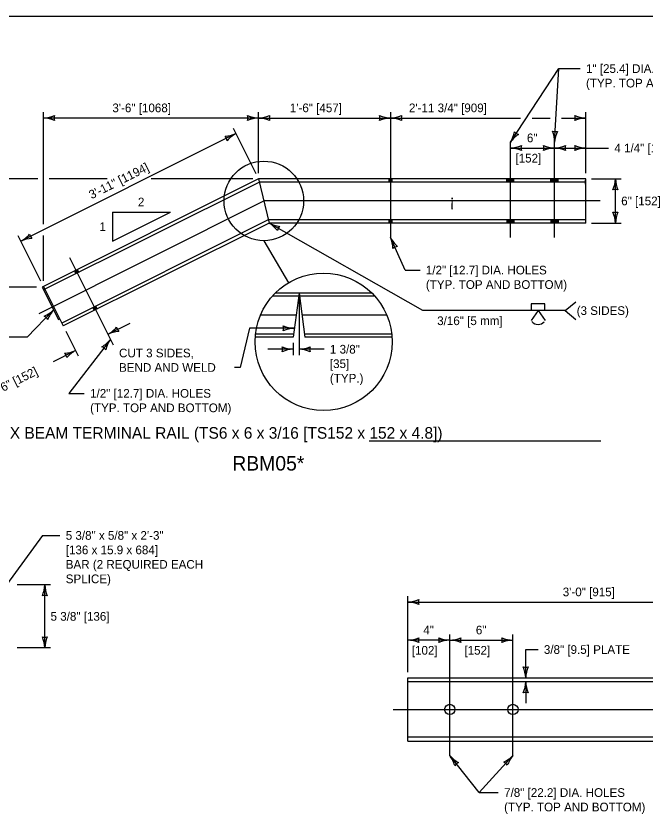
# Model space of a CAD drawing. Extents: x 49991.4 to 50021, y 49987.6 to 50011.4.
# Drawn here: x 50009.79 to 50014.14, y 49993.45 to 49999 of the extents above; entities that cross this region are included whole.
import ezdxf

# ---------------------------------------------------------------- set-up
doc = ezdxf.new("R2010")
doc.units = 0
for name, color, linetype in [('Level 1', 7, 'Continuous'), ('Level 2', 7, 'Continuous'), ('Level 3', 7, 'Continuous'), ('Level 4', 7, 'Continuous'), ('Level 5', 7, 'Continuous')]:
    doc.layers.add(name, color=color, linetype=linetype)

msp = doc.modelspace()

# ---------------------------------------------------------------- linework, layer by layer
at = {"layer": 'Level 1'}
for p, q in [((50011.4634, 49997.8746), (50009.9679, 49997.1269)), ((50011.4634, 49997.8746), (50011.5353, 49997.5698)), ((50013.2106, 49997.8746), (50011.4634, 49997.8746)), ((50013.7246, 49997.8746), (50013.2108, 49997.8746)), ((50013.7246, 49997.5698), (50013.7246, 49997.8746)), ((50011.5353, 49997.5698), (50010.1132, 49996.8588)), ((50013.2106, 49997.5698), (50011.5353, 49997.5698)), ((50013.7246, 49997.5698), (50013.2109, 49997.5698)), ((50009.9769, 49997.1314), (50009.9679, 49997.1269)), ((50009.9679, 49997.1269), (50010.08, 49996.9027)), ((50009.9769, 49997.1314), (50010.1132, 49996.8588)), ((50012.2451, 49997.0864), (50011.5793, 49997.0864)), ((50011.7426, 49997.0864), (50011.7014, 49996.7816)), ((50011.7426, 49997.0864), (50011.7839, 49996.7816)), ((50010.08, 49996.9027), (50010.089, 49996.9072)), ((50011.7014, 49996.7816), (50011.4395, 49996.7816)), ((50012.3849, 49996.7816), (50011.7839, 49996.7816)), ((50012.4943, 49994.4284), (50015.1145, 49994.4284)), ((50012.4943, 49993.9918), (50012.4943, 49994.4284)), ((50012.4943, 49993.9918), (50015.1145, 49993.9918))]:
    msp.add_line(p, q, dxfattribs=at)
msp.add_lwpolyline([(49999.3835, 49998.9992), (50016.7501, 49998.9992), (50016.7501, 49987.7988), (49999.3835, 49987.7988)], close=True, dxfattribs=at)
for centre in [(50012.7844, 49994.21), (50013.2211, 49994.21)]:
    msp.add_circle(centre, 0.0356, dxfattribs=at)
at = {"layer": 'Level 2'}
msp.add_line((50012.228, 49996.0643), (50013.8293, 49996.0643), dxfattribs=at)
at = {"layer": 'Level 3'}
for p, q in [((50013.2033, 49998.1278), (50013.538, 49998.6364)), ((50013.5079, 49998.1278), (50013.538, 49998.6364)), ((50013.538, 49998.6364), (50013.6861, 49998.6364)), ((50009.9769, 49997.5627), (50009.9769, 49998.3351)), ((50011.4634, 49998.2951), (50009.9769, 49998.2951)), ((50011.4634, 49997.9146), (50011.4634, 49998.3351)), ((50011.4634, 49998.2951), (50012.3758, 49998.2951)), ((50012.3758, 49998.2951), (50013.2734, 49998.2951)), ((50013.3534, 49998.2951), (50013.4778, 49998.2951)), ((50013.5578, 49998.2951), (50013.7246, 49998.2951)), ((50013.7246, 49997.9146), (50013.7246, 49998.3351)), ((50011.3068, 49998.1877), (50009.8203, 49997.4444)), ((50011.4455, 49997.9104), (50011.289, 49998.2235)), ((50013.2033, 49998.0878), (50013.5079, 49998.0878)), ((50013.5079, 49998.0878), (50013.7246, 49998.0878)), ((50013.7246, 49998.0878), (50013.8821, 49998.0878)), ((50009.9369, 49997.8746), (50009.5533, 49997.8746)), ((50010.4161, 49997.8746), (50010.0169, 49997.8746)), ((50011.4234, 49997.8746), (50010.7207, 49997.8746)), ((50013.7646, 49997.8746), (50013.9694, 49997.8746)), ((50013.9294, 49997.5698), (50013.9294, 49997.8746)), ((50010.4537, 49997.6451), (50010.4537, 49997.4446)), ((50010.4537, 49997.6451), (50010.8548, 49997.6451)), ((50010.4537, 49997.4446), (50010.8548, 49997.6451)), ((50012.5977, 49996.9648), (50011.5353, 49997.5698)), ((50013.7646, 49997.5698), (50013.9694, 49997.5698)), ((50009.959, 49997.1672), (50009.8025, 49997.4802)), ((50009.9769, 49997.1714), (50009.9769, 49997.4827)), ((50012.4762, 49997.2448), (50012.3758, 49997.4698)), ((50012.3804, 49997.4595), (50012.3804, 49997.4595)), ((50011.4993, 49997.4476), (50011.6694, 49997.156)), ((50012.4762, 49997.2448), (50012.5792, 49997.2448)), ((50009.9279, 49997.1269), (50009.5533, 49997.1269)), ((50013.3481, 49997.012), (50013.3481, 49996.9648)), ((50013.4414, 49997.012), (50013.3481, 49997.012)), ((50013.4414, 49996.9648), (50013.4414, 49997.012)), ((50013.5816, 49996.9648), (50013.6548, 49997.0262)), ((50010.0467, 49996.9693), (50009.8642, 49996.7819)), ((50013.5816, 49996.9648), (50012.5977, 49996.9648)), ((50013.3948, 49996.9648), (50013.3463, 49996.8971)), ((50013.3948, 49996.9648), (50013.4433, 49996.8971)), ((50013.5816, 49996.9648), (50013.6548, 49996.9034)), ((50010.4216, 49996.801), (50010.5767, 49996.8786)), ((50011.4008, 49996.8428), (50011.336, 49996.572)), ((50011.7097, 49996.8428), (50011.4008, 49996.8428)), ((50010.1311, 49996.823), (50010.2159, 49996.6534)), ((50009.8642, 49996.7819), (50009.7393, 49996.7819)), ((50010.4395, 49996.7652), (50010.1522, 49996.3934)), ((50011.7014, 49996.7416), (50011.7014, 49996.658)), ((50010.198, 49996.6892), (50010.0429, 49996.6117)), ((50011.7014, 49996.698), (50011.528, 49996.698)), ((50011.916, 49996.698), (50011.7426, 49996.698)), ((50011.336, 49996.572), (50011.296, 49996.572)), ((50010.1522, 49996.3934), (50010.2587, 49996.3934)), ((50012.4941, 49994.4684), (50012.4941, 49994.9918)), ((50012.4943, 49994.9518), (50015.1173, 49994.9518)), ((50012.7844, 49994.6885), (50012.4941, 49994.6885)), ((50012.7844, 49994.6885), (50013.2211, 49994.6885)), ((50013.3095, 49994.4284), (50013.3095, 49994.6238)), ((50013.3095, 49994.6238), (50013.3949, 49994.6238)), ((50013.3095, 49994.4012), (50013.3095, 49994.2528)), ((50012.9874, 49993.6359), (50012.7844, 49993.8918)), ((50012.9874, 49993.6359), (50013.2211, 49993.8918)), ((50012.9874, 49993.636), (50013.12, 49993.636))]:
    msp.add_line(p, q, dxfattribs=at)
for points in [[(50009.969, 49995.4121), (50009.7202, 49995.0713)], [(50009.969, 49995.4121), (50010.0904, 49995.4121)], [(50010.0254, 49995.0713), (50009.7954, 49995.0713)], [(50009.9854, 49994.6345), (50009.9854, 49995.0713)], [(50010.0254, 49994.6345), (50009.7954, 49994.6345)]]:
    msp.add_lwpolyline(points, dxfattribs=at)
for centre, radius in [((50011.4993, 49997.7222), 0.2747), ((50011.9122, 49996.7492), 0.4738)]:
    msp.add_circle(centre, radius, dxfattribs=at)
for centre, radius, start, end in [((50009.9677, 49998.5172), 0.2223, 272.3605, 292.544), ((50009.9654, 49998.0624), 0.233, 67.9228, 87.1727), ((50010.1051, 49998.2951), 0.0548, 162.1388, 197.8612), ((50011.3352, 49998.2951), 0.0548, 342.1388, 17.8612), ((50011.4749, 49998.5278), 0.233, 247.9228, 267.1727), ((50011.4725, 49998.0729), 0.2223, 92.3605, 112.544), ((50011.4542, 49998.5172), 0.2223, 272.3605, 292.544), ((50011.4519, 49998.0624), 0.233, 67.9228, 87.1727), ((50011.5916, 49998.2951), 0.0548, 162.1388, 197.8612), ((50012.2475, 49998.2951), 0.0548, 342.1388, 17.8612), ((50012.3873, 49998.5278), 0.233, 247.9228, 267.1727), ((50012.3849, 49998.0729), 0.2223, 92.3605, 112.544), ((50012.3666, 49998.5172), 0.2223, 272.3605, 292.544), ((50012.3643, 49998.0624), 0.233, 67.9228, 87.1727), ((50012.504, 49998.2951), 0.0548, 162.1388, 197.8612), ((50013.5964, 49998.2951), 0.0548, 342.1388, 17.8612), ((50013.7361, 49998.5278), 0.233, 247.9228, 267.1727), ((50013.7337, 49998.0729), 0.2223, 92.3605, 112.544), ((50011.213, 49998.401), 0.233, 274.4879, 293.7377), ((50011.4144, 49997.9931), 0.2223, 118.9255, 139.109), ((50013.0026, 49998.2461), 0.233, 329.4806, 348.7305), ((50013.3839, 49997.9981), 0.2223, 124.1093, 144.2928), ((50013.2738, 49998.2349), 0.0548, 218.7921, 254.5145), ((50013.5155, 49998.2558), 0.0548, 248.751, 284.4734), ((50013.2749, 49998.1301), 0.233, 359.4395, 18.6894), ((50013.7291, 49998.1056), 0.2223, 154.0682, 174.2517), ((50011.1922, 49998.1303), 0.0548, 8.7039, 44.4262), ((50013.1942, 49998.31), 0.2223, 272.3605, 292.544), ((50013.1918, 49997.8551), 0.233, 67.9228, 87.1727), ((50013.3316, 49998.0878), 0.0548, 162.1388, 197.8612), ((50013.3797, 49998.0878), 0.0548, 342.1388, 17.8612), ((50013.5194, 49998.3205), 0.233, 247.9228, 267.1727), ((50013.517, 49997.8657), 0.2223, 92.3605, 112.544), ((50013.4987, 49998.31), 0.2223, 272.3605, 292.544), ((50013.4964, 49997.8551), 0.233, 67.9228, 87.1727), ((50013.6361, 49998.0878), 0.0548, 162.1388, 197.8612), ((50013.5964, 49998.0878), 0.0548, 342.1388, 17.8612), ((50013.7361, 49998.3205), 0.233, 247.9228, 267.1727), ((50013.7337, 49997.8657), 0.2223, 92.3605, 112.544), ((50013.6967, 49997.8861), 0.233, 337.9228, 357.1727), ((50014.1516, 49997.8838), 0.2223, 182.3605, 202.544), ((50013.9294, 49997.7464), 0.0548, 72.1388, 107.8612), ((50013.7073, 49997.5607), 0.2223, 2.3605, 22.544), ((50013.9294, 49997.698), 0.0548, 252.1388, 287.8612), ((50014.1622, 49997.5583), 0.233, 157.9228, 177.1727), ((50011.6373, 49997.7674), 0.2223, 242.6979, 262.8814), ((50011.4102, 49997.3733), 0.233, 38.2602, 57.5101), ((50011.6467, 49997.5064), 0.0548, 132.4762, 168.1986), ((50009.7128, 49997.639), 0.2223, 298.9255, 319.109), ((50009.9141, 49997.2312), 0.233, 94.4879, 113.7377), ((50009.935, 49997.5018), 0.0548, 188.7039, 224.4262), ((50012.1692, 49997.3876), 0.2223, 1.5178, 21.7013), ((50012.5836, 49997.5752), 0.233, 206.8891, 226.139), ((50012.428, 49997.3528), 0.0548, 96.2006, 131.923), ((50009.888, 49997.1399), 0.233, 293.6888, 312.9386), ((50010.2123, 49996.8209), 0.2223, 138.1264, 158.3099), ((50009.9573, 49996.8774), 0.0548, 27.9048, 63.6271), ((50010.3072, 49997.004), 0.233, 299.3924, 318.6422), ((50010.5363, 49996.8584), 0.0548, 188.7039, 224.4262), ((50011.5815, 49996.8428), 0.0548, 342.1388, 17.8612), ((50011.7212, 49997.0755), 0.233, 247.9228, 267.1727), ((50011.7188, 49996.6206), 0.2223, 92.3605, 112.544), ((50013.395, 49996.9255), 0.0566, 220.7558, 318.7312), ((50010.5127, 49996.5982), 0.2223, 94.0211, 114.2046), ((50010.2693, 49996.9083), 0.2223, 299.7681, 319.9516), ((50010.6307, 49996.6321), 0.233, 145.1394, 164.3893), ((50010.1068, 49996.892), 0.2223, 274.0211, 294.2046), ((50010.3123, 49996.4862), 0.233, 119.3924, 138.6422), ((50010.3611, 49996.6638), 0.0548, 34.4509, 70.1733), ((50011.5732, 49996.698), 0.0548, 342.1388, 17.8612), ((50011.7129, 49996.9307), 0.233, 247.9228, 267.1727), ((50011.7106, 49996.4759), 0.2223, 92.3605, 112.544), ((50011.7335, 49996.9202), 0.2223, 272.3605, 292.544), ((50011.7311, 49996.4653), 0.233, 67.9228, 87.1727), ((50011.8709, 49996.698), 0.0548, 162.1388, 197.8612), ((50010.0833, 49996.6319), 0.0548, 8.7039, 44.4262), ((50009.7633, 49995.0805), 0.2223, 337.456, 357.6395), ((50010.2181, 49995.0828), 0.233, 182.8273, 202.0772), ((50009.9854, 49994.9431), 0.0548, 72.1388, 107.8612), ((50012.4827, 49995.1845), 0.233, 272.8273, 292.0772), ((50012.6224, 49994.9518), 0.0548, 162.1388, 197.8612), ((50012.485, 49994.7297), 0.2223, 67.456, 87.6395), ((50009.9854, 49994.7627), 0.0548, 252.1388, 287.8612), ((50009.7527, 49994.623), 0.233, 2.8273, 22.0772), ((50010.2076, 49994.6253), 0.2223, 157.456, 177.6395), ((50012.4827, 49994.9212), 0.233, 272.8273, 292.0772), ((50012.485, 49994.4663), 0.2223, 67.456, 87.6395), ((50012.6224, 49994.6885), 0.0548, 162.1388, 197.8612), ((50012.7936, 49994.9106), 0.2223, 247.456, 267.6395), ((50012.6562, 49994.6885), 0.0548, 342.1388, 17.8612), ((50012.7959, 49994.4558), 0.233, 92.8273, 112.0772), ((50012.7729, 49994.9212), 0.233, 272.8273, 292.0772), ((50012.7753, 49994.4663), 0.2223, 67.456, 87.6395), ((50012.9126, 49994.6885), 0.0548, 162.1388, 197.8612), ((50013.2303, 49994.9106), 0.2223, 247.456, 267.6395), ((50013.0929, 49994.6885), 0.0548, 342.1388, 17.8612), ((50013.2326, 49994.4558), 0.233, 92.8273, 112.0772), ((50013.3095, 49994.5566), 0.0548, 252.1388, 287.8612), ((50013.0768, 49994.4169), 0.233, 2.8273, 22.0772), ((50013.5317, 49994.4192), 0.2223, 157.456, 177.6395), ((50013.0874, 49994.4104), 0.2223, 337.456, 357.6395), ((50013.5422, 49994.4127), 0.233, 182.8273, 202.0772), ((50013.3095, 49994.273), 0.0548, 72.1388, 107.8612), ((50012.6047, 49993.7609), 0.2223, 15.8845, 36.068), ((50012.9596, 49994.0454), 0.233, 221.2558, 240.5056), ((50013.0633, 49994.0483), 0.2223, 295.0486, 315.2321), ((50013.1347, 49993.7971), 0.0548, 29.7314, 65.4538), ((50013.4007, 49993.7433), 0.233, 140.4199, 159.6697), ((50012.8641, 49993.7913), 0.0548, 110.5673, 146.2897)]:
    msp.add_arc(centre, radius, start, end, dxfattribs=at)
at = {"layer": 'Level 4'}
for p, q in [((50011.4684, 49997.8531), (50009.9775, 49997.1077)), ((50013.7246, 49997.8531), (50011.4684, 49997.8531)), ((50012.3649, 49997.8531), (50012.3649, 49997.8746)), ((50012.3869, 49997.8689), (50012.3649, 49997.8689)), ((50012.3869, 49997.8639), (50012.3649, 49997.8639)), ((50012.3869, 49997.8589), (50012.3649, 49997.8589)), ((50012.3869, 49997.8531), (50012.3869, 49997.8746)), ((50013.1786, 49997.8531), (50013.1786, 49997.8747)), ((50013.2281, 49997.8689), (50013.1786, 49997.8689)), ((50013.2281, 49997.8639), (50013.1786, 49997.8639)), ((50013.2281, 49997.8589), (50013.1786, 49997.8589)), ((50013.2281, 49997.8531), (50013.2281, 49997.8747)), ((50013.4831, 49997.8531), (50013.4831, 49997.8746)), ((50013.5326, 49997.8689), (50013.4831, 49997.8689)), ((50013.5326, 49997.8639), (50013.4831, 49997.8639)), ((50013.5326, 49997.8589), (50013.4831, 49997.8589)), ((50013.5326, 49997.8531), (50013.5326, 49997.8746)), ((50013.7228, 49997.8383), (50013.7228, 49997.8653)), ((50011.5302, 49997.5913), (50010.1036, 49996.878)), ((50013.7246, 49997.5913), (50011.5302, 49997.5913)), ((50012.3649, 49997.5698), (50012.3649, 49997.5913)), ((50012.3869, 49997.5856), (50012.3649, 49997.5856)), ((50012.3869, 49997.5806), (50012.3649, 49997.5806)), ((50012.3869, 49997.5756), (50012.3649, 49997.5756)), ((50012.3869, 49997.5698), (50012.3869, 49997.5913)), ((50013.1786, 49997.5913), (50013.1786, 49997.5699)), ((50013.2281, 49997.5856), (50013.1786, 49997.5856)), ((50013.2281, 49997.5806), (50013.1786, 49997.5806)), ((50013.2281, 49997.5756), (50013.1786, 49997.5756)), ((50013.2281, 49997.5913), (50013.2281, 49997.5699)), ((50013.4831, 49997.5913), (50013.4831, 49997.5698)), ((50013.5326, 49997.5856), (50013.4831, 49997.5856)), ((50013.5326, 49997.5806), (50013.4831, 49997.5806)), ((50013.5326, 49997.5756), (50013.4831, 49997.5756)), ((50013.5326, 49997.5913), (50013.5326, 49997.5698)), ((50013.7228, 49997.6065), (50013.7228, 49997.5795)), ((50010.1908, 49997.2383), (50010.2004, 49997.2191)), ((50010.2128, 49997.2429), (50010.1933, 49997.2332)), ((50010.2151, 49997.2385), (50010.1956, 49997.2287)), ((50010.2173, 49997.234), (50010.1978, 49997.2242)), ((50010.2102, 49997.2481), (50010.2199, 49997.2288)), ((50011.7397, 49997.0649), (50011.5589, 49997.0649)), ((50012.2656, 49997.0649), (50011.7455, 49997.0649)), ((50010.3174, 49996.9849), (50010.3271, 49996.9657)), ((50010.3395, 49996.9895), (50010.32, 49996.9798)), ((50010.3418, 49996.9851), (50010.3223, 49996.9753)), ((50010.344, 49996.9806), (50010.3245, 49996.9708)), ((50010.3369, 49996.9947), (50010.3466, 49996.9755)), ((50011.7043, 49996.8031), (50011.4415, 49996.8031)), ((50012.3829, 49996.8031), (50011.781, 49996.8031)), ((50015.1145, 49994.4012), (50012.4943, 49994.4012)), ((50015.1145, 49994.0196), (50012.4943, 49994.0196))]:
    msp.add_line(p, q, dxfattribs=at)
at = {"layer": 'Level 5'}
for p, q in [((50012.3758, 49998.3351), (50012.3758, 49997.4698)), ((50013.2033, 49997.4698), (50013.2033, 49998.1278)), ((50013.5079, 49997.4698), (50013.5079, 49998.1278)), ((50009.9466, 49996.9459), (50011.4993, 49997.7222)), ((50013.8246, 49997.7222), (50011.4993, 49997.7222)), ((50010.1558, 49997.3326), (50010.4574, 49996.7295)), ((50011.7426, 49997.0735), (50011.7426, 49996.658)), ((50011.722, 49996.9339), (50011.4759, 49996.9339)), ((50012.3485, 49996.9339), (50011.7633, 49996.9339)), ((50012.7844, 49993.8918), (50012.7844, 49994.7285)), ((50013.2211, 49993.8918), (50013.2211, 49994.7285)), ((50012.3943, 49994.2102), (50015.2145, 49994.2102))]:
    msp.add_line(p, q, dxfattribs=at)

# ---------------------------------------------------------------- texts
at = {"layer": 'Level 2'}
for s, height, p in [('1" [25.4] DIA. HOLES ', 0.06, (50013.7261, 49998.6064)), ('(TYP. TOP AND BOTTOM)', 0.06, (50013.7261, 49998.5064)), ('3\'-6" [1068]', 0.06, (50010.4526, 49998.3351)), ('1\'-6" [457]', 0.06, (50011.679, 49998.3351)), ('2\'-11 3/4" [909]', 0.06, (50012.5022, 49998.3351)), ('6"', 0.06, (50013.3176, 49998.1278)), ('4 1/4" [108]', 0.06, (50013.9221, 49998.0578)), ('[152]', 0.06, (50013.2385, 49997.9878)), ('2', 0.06, (50010.6291, 49997.6851)), ('¡', 0.08, (50012.7829, 49997.6824)), ('6" [152]', 0.06, (50013.9694, 49997.6922)), ('1 ', 0.06, (50010.3637, 49997.5149)), ('1/2" [12.7] DIA. HOLES', 0.06, (50012.6192, 49997.2148)), ('(TYP. TOP AND BOTTOM)', 0.06, (50012.6192, 49997.1148)), ('(3 SIDES)', 0.06, (50013.6616, 49996.9348)), (' 3/16" [5 mm]', 0.06, (50012.6753, 49996.8648)), ('1 3/8"', 0.06, (50011.956, 49996.668)), ('CUT 3 SIDES,', 0.06, (50010.4987, 49996.642)), ('[35]', 0.06, (50011.956, 49996.568)), ('BEND AND WELD', 0.06, (50010.4987, 49996.542)), ('(TYP.)', 0.06, (50011.956, 49996.468)), ('1/2" [12.7] DIA. HOLES ', 0.06, (50010.2987, 49996.3634)), ('(TYP. TOP AND BOTTOM)', 0.06, (50010.2987, 49996.2634)), ('BOX BEAM TERMINAL RAIL (TS6 x 6 x 3/16 [TS152 x 152 x 4.8])', 0.08, (50009.5893, 49996.0801)), ('RBM05*', 0.1, (50011.2815, 49995.8601)), ('5 3/8" x 5/8" x 2\'-3" ', 0.06, (50010.1304, 49995.3821)), ('[136 x 15.9 x 684]', 0.06, (50010.1304, 49995.2821)), ('BAR (2 REQUIRED EACH', 0.06, (50010.1304, 49995.1821)), ('SPLICE)', 0.06, (50010.1304, 49995.0821)), ('3\'-0" [915]', 0.06, (50013.5653, 49994.9918)), ('5 3/8" [136]', 0.06, (50010.0254, 49994.8229)), ('4"', 0.06, (50012.6013, 49994.7285)), ('6"', 0.06, (50012.9648, 49994.7285)), ('[102]', 0.06, (50012.5221, 49994.5885)), ('[152]', 0.06, (50012.8856, 49994.5885)), ('3/8" [9.5] PLATE', 0.06, (50013.4349, 49994.5938)), ('7/8" [22.2] DIA. HOLES', 0.06, (50013.16, 49993.606)), ('(TYP. TOP AND BOTTOM)', 0.06, (50013.16, 49993.506))]:
    msp.add_text(s, height=height, dxfattribs=at).set_placement(p)
for s, p in [('3\'-11" [1194]', (50010.3093, 49997.7336)), ('6" [152]', (50009.6979, 49996.4032))]:
    msp.add_text(s, height=0.06, rotation=26.5651, dxfattribs=at).set_placement(p)

doc.saveas('drawing.dxf')
